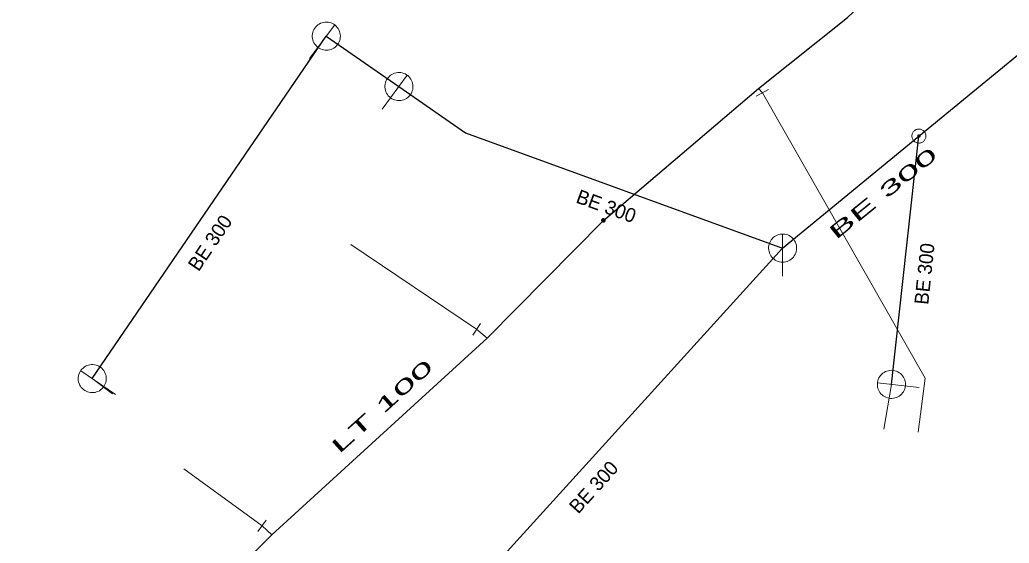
# Model space of a CAD drawing. Extents: x -791337 to -790755, y -988454 to -987923.
# Drawn here: x -791100.6 to -791030.1, y -988190.7 to -988153.5 of the extents above; entities that cross this region are included whole.
import ezdxf

# ---------------------------------------------------------------- set-up
doc = ezdxf.new("R2010")
doc.units = 0
doc.header["$LTSCALE"] = 0.4
for name, color, linetype, lineweight in [('1', 7, 'Continuous', 13), ('11', 7, 'Continuous', 13), ('13', 7, 'Continuous', 13), ('14', 7, 'Continuous', 25), ('17', 7, 'Continuous', 25), ('22', 7, 'Continuous', 13), ('31', 7, 'Continuous', 13), ('34', 7, 'Continuous', 13), ('9', 7, 'Continuous', 13)]:
    doc.layers.add(name, color=color, linetype=linetype, lineweight=lineweight)

msp = doc.modelspace()

# ---------------------------------------------------------------- linework, layer by layer
at = {"layer": '11'}
for p, q in [((-791093.973, -988180.094), (-791095.423, -988179.006)), ((-791038.989, -988182.596), (-791038.46, -988179.417))]:
    msp.add_line(p, q, dxfattribs=at)
at = {"layer": '13'}
for p, q in [((-791068.026, -988175.492), (-791076.987, -988169.447)), ((-791067.283, -988176.118), (-791068.026, -988175.492)), ((-791083.315, -988189.494), (-791088.895, -988185.436)), ((-791082.624, -988190.124), (-791083.315, -988189.494))]:
    msp.add_line(p, q, dxfattribs=at)
msp.add_lwpolyline([(-791047.659, -988158.659), (-791036.061, -988178.975), (-791036.548, -988182.811)], dxfattribs=at)
at = {"layer": '14', "lineweight": 13}
msp.add_line((-791047.931, -988158.352), (-791047.659, -988158.659), dxfattribs=at)
at = {"layer": '14'}
msp.add_line((-791046.212, -988169.71), (-791036.499, -988161.736), dxfattribs=at)
for points in [[(-791038.46, -988179.417), (-791036.499, -988161.736), (-791017.401, -988146.056)], [(-791095.423, -988179.006), (-791078.737, -988154.618), (-791073.562, -988158.21)], [(-791073.562, -988158.21), (-791068.822, -988161.5), (-791046.212, -988169.71)], [(-791078.328, -988268.275), (-791076.412, -988241.781), (-791075.638, -988228.634), (-791074.254, -988200.572), (-791046.212, -988169.71)]]:
    msp.add_lwpolyline(points, dxfattribs=at)
at = {"layer": '17'}
for points in [[(-791058.988, -988167.736), (-791047.931, -988158.352), (-791041.594, -988153.292), (-791025.772, -988138.449), (-791015.996, -988126.782)], [(-791100.587, -988208.045), (-791094.248, -988201.857), (-791082.624, -988190.124), (-791067.283, -988176.118), (-791058.988, -988167.736)]]:
    msp.add_lwpolyline(points, dxfattribs=at)
at = {"layer": '22'}
for p, q in [((-791079.931, -988156.222), (-791078.14, -988153.816)), ((-791074.756, -988159.814), (-791072.965, -988157.408)), ((-791046.212, -988171.711), (-791046.211, -988168.711)), ((-791093.771, -988180.135), (-791096.247, -988178.441)), ((-791036.471, -988179.637), (-791039.453, -988179.306))]:
    msp.add_line(p, q, dxfattribs=at)
for points in [[(-791077.935, -988155.215), (-791077.874, -988155.124), (-791077.824, -988155.026), (-791077.785, -988154.924), (-791077.757, -988154.819), (-791077.741, -988154.71), (-791077.737, -988154.601), (-791077.745, -988154.491), (-791077.765, -988154.384), (-791077.796, -988154.278), (-791077.839, -988154.178), (-791077.892, -988154.082), (-791077.957, -988153.993), (-791078.029, -988153.912), (-791078.111, -988153.839), (-791078.2, -988153.774), (-791078.295, -988153.721), (-791078.396, -988153.677), (-791078.501, -988153.646), (-791078.609, -988153.626), (-791078.717, -988153.618), (-791078.827, -988153.622), (-791078.935, -988153.638), (-791079.042, -988153.666), (-791079.144, -988153.704), (-791079.241, -988153.754), (-791079.332, -988153.815), (-791079.417, -988153.885), (-791079.492, -988153.963), (-791079.56, -988154.05), (-791079.617, -988154.144), (-791079.664, -988154.242), (-791079.699, -988154.346), (-791079.723, -988154.452), (-791079.736, -988154.561), (-791079.735, -988154.671), (-791079.724, -988154.78), (-791079.7, -988154.887), (-791079.665, -988154.991), (-791079.619, -988155.09), (-791079.561, -988155.183), (-791079.495, -988155.27), (-791079.419, -988155.349), (-791079.335, -988155.42), (-791079.244, -988155.48), (-791079.146, -988155.53), (-791079.045, -988155.569), (-791078.938, -988155.597), (-791078.829, -988155.613), (-791078.72, -988155.617), (-791078.611, -988155.61), (-791078.503, -988155.591), (-791078.399, -988155.559), (-791078.298, -988155.517), (-791078.203, -988155.463), (-791078.113, -988155.4), (-791078.031, -988155.326), (-791077.958, -988155.245)], [(-791072.76, -988158.807), (-791072.699, -988158.716), (-791072.649, -988158.618), (-791072.61, -988158.516), (-791072.582, -988158.411), (-791072.566, -988158.302), (-791072.562, -988158.193), (-791072.57, -988158.083), (-791072.59, -988157.976), (-791072.621, -988157.87), (-791072.664, -988157.77), (-791072.717, -988157.674), (-791072.782, -988157.585), (-791072.854, -988157.504), (-791072.936, -988157.431), (-791073.025, -988157.366), (-791073.12, -988157.313), (-791073.221, -988157.269), (-791073.326, -988157.238), (-791073.434, -988157.218), (-791073.542, -988157.21), (-791073.652, -988157.214), (-791073.76, -988157.23), (-791073.867, -988157.258), (-791073.969, -988157.296), (-791074.066, -988157.346), (-791074.157, -988157.407), (-791074.242, -988157.477), (-791074.317, -988157.555), (-791074.385, -988157.642), (-791074.442, -988157.736), (-791074.489, -988157.834), (-791074.524, -988157.938), (-791074.548, -988158.044), (-791074.561, -988158.153), (-791074.56, -988158.263), (-791074.549, -988158.372), (-791074.525, -988158.479), (-791074.49, -988158.583), (-791074.444, -988158.682), (-791074.386, -988158.775), (-791074.32, -988158.862), (-791074.244, -988158.941), (-791074.16, -988159.012), (-791074.069, -988159.072), (-791073.971, -988159.122), (-791073.87, -988159.161), (-791073.763, -988159.189), (-791073.654, -988159.205), (-791073.545, -988159.209), (-791073.436, -988159.202), (-791073.328, -988159.183), (-791073.224, -988159.151), (-791073.123, -988159.109), (-791073.028, -988159.055), (-791072.938, -988158.992), (-791072.856, -988158.918), (-791072.783, -988158.837)], [(-791045.212, -988169.711), (-791045.217, -988169.602), (-791045.235, -988169.494), (-791045.265, -988169.388), (-791045.305, -988169.287), (-791045.357, -988169.19), (-791045.419, -988169.1), (-791045.491, -988169.017), (-791045.571, -988168.943), (-791045.659, -988168.877), (-791045.753, -988168.822), (-791045.853, -988168.777), (-791045.958, -988168.744), (-791046.065, -988168.722), (-791046.174, -988168.712), (-791046.284, -988168.714), (-791046.392, -988168.728), (-791046.499, -988168.753), (-791046.602, -988168.79), (-791046.7, -988168.839), (-791046.792, -988168.897), (-791046.878, -988168.966), (-791046.955, -988169.043), (-791047.024, -988169.129), (-791047.083, -988169.221), (-791047.131, -988169.319), (-791047.168, -988169.422), (-791047.194, -988169.529), (-791047.208, -988169.637), (-791047.211, -988169.747), (-791047.201, -988169.856), (-791047.18, -988169.963), (-791047.146, -988170.067), (-791047.102, -988170.167), (-791047.047, -988170.262), (-791046.981, -988170.35), (-791046.907, -988170.43), (-791046.824, -988170.502), (-791046.734, -988170.564), (-791046.638, -988170.616), (-791046.536, -988170.657), (-791046.431, -988170.687), (-791046.323, -988170.705), (-791046.213, -988170.711), (-791046.104, -988170.705), (-791045.996, -988170.687), (-791045.891, -988170.658), (-791045.789, -988170.617), (-791045.692, -988170.565), (-791045.602, -988170.503), (-791045.519, -988170.432), (-791045.444, -988170.352), (-791045.379, -988170.264), (-791045.323, -988170.17), (-791045.279, -988170.07), (-791045.245, -988169.966), (-791045.223, -988169.858), (-791045.213, -988169.749)], [(-791094.857, -988178.18), (-791094.951, -988178.124), (-791095.05, -988178.078), (-791095.154, -988178.043), (-791095.26, -988178.019), (-791095.37, -988178.007), (-791095.479, -988178.007), (-791095.588, -988178.02), (-791095.695, -988178.044), (-791095.799, -988178.079), (-791095.897, -988178.126), (-791095.991, -988178.183), (-791096.077, -988178.251), (-791096.156, -988178.327), (-791096.226, -988178.411), (-791096.286, -988178.503), (-791096.336, -988178.6), (-791096.375, -988178.703), (-791096.403, -988178.808), (-791096.418, -988178.917), (-791096.422, -988179.026), (-791096.414, -988179.136), (-791096.394, -988179.243), (-791096.362, -988179.348), (-791096.319, -988179.449), (-791096.265, -988179.544), (-791096.201, -988179.632), (-791096.127, -988179.714), (-791096.046, -988179.787), (-791095.956, -988179.851), (-791095.861, -988179.904), (-791095.761, -988179.947), (-791095.656, -988179.978), (-791095.548, -988179.998), (-791095.439, -988180.006), (-791095.329, -988180.001), (-791095.221, -988179.985), (-791095.115, -988179.958), (-791095.013, -988179.918), (-791094.916, -988179.868), (-791094.824, -988179.807), (-791094.74, -988179.738), (-791094.664, -988179.659), (-791094.597, -988179.571), (-791094.541, -988179.478), (-791094.495, -988179.379), (-791094.459, -988179.276), (-791094.435, -988179.168), (-791094.424, -988179.059), (-791094.424, -988178.95), (-791094.436, -988178.841), (-791094.459, -988178.734), (-791094.495, -988178.631), (-791094.541, -988178.531), (-791094.599, -988178.438), (-791094.666, -988178.352), (-791094.742, -988178.273), (-791094.827, -988178.203)], [(-791038.349, -988178.423), (-791038.458, -988178.417), (-791038.567, -988178.423), (-791038.676, -988178.441), (-791038.781, -988178.469), (-791038.883, -988178.51), (-791038.979, -988178.562), (-791039.069, -988178.624), (-791039.152, -988178.696), (-791039.227, -988178.776), (-791039.292, -988178.863), (-791039.348, -988178.958), (-791039.392, -988179.059), (-791039.426, -988179.162), (-791039.448, -988179.27), (-791039.458, -988179.379), (-791039.456, -988179.488), (-791039.443, -988179.597), (-791039.417, -988179.704), (-791039.38, -988179.806), (-791039.332, -988179.904), (-791039.273, -988179.997), (-791039.205, -988180.082), (-791039.127, -988180.16), (-791039.042, -988180.229), (-791038.95, -988180.288), (-791038.852, -988180.336), (-791038.748, -988180.374), (-791038.642, -988180.399), (-791038.533, -988180.413), (-791038.424, -988180.416), (-791038.315, -988180.406), (-791038.208, -988180.384), (-791038.104, -988180.351), (-791038.003, -988180.307), (-791037.909, -988180.251), (-791037.821, -988180.187), (-791037.74, -988180.112), (-791037.669, -988180.029), (-791037.606, -988179.94), (-791037.554, -988179.843), (-791037.513, -988179.742), (-791037.483, -988179.636), (-791037.465, -988179.528), (-791037.459, -988179.419), (-791037.465, -988179.309), (-791037.482, -988179.202), (-791037.512, -988179.096), (-791037.553, -988178.994), (-791037.605, -988178.898), (-791037.666, -988178.807), (-791037.737, -988178.724), (-791037.818, -988178.65), (-791037.905, -988178.584), (-791037.999, -988178.529), (-791038.099, -988178.484), (-791038.204, -988178.45), (-791038.311, -988178.428)]]:
    msp.add_lwpolyline(points, close=True, dxfattribs=at)
at = {"layer": '31'}
for points in [[(-791036.443, -988161.239), (-791036.495, -988161.236), (-791036.548, -988161.238), (-791036.599, -988161.246), (-791036.65, -988161.259), (-791036.699, -988161.278), (-791036.746, -988161.302), (-791036.79, -988161.33), (-791036.83, -988161.363), (-791036.868, -988161.399), (-791036.901, -988161.439), (-791036.93, -988161.483), (-791036.954, -988161.53), (-791036.973, -988161.578), (-791036.987, -988161.629), (-791036.995, -988161.68), (-791036.998, -988161.732), (-791036.996, -988161.785), (-791036.988, -988161.837), (-791036.975, -988161.887), (-791036.956, -988161.936), (-791036.932, -988161.983), (-791036.904, -988162.028), (-791036.871, -988162.068), (-791036.835, -988162.106), (-791036.795, -988162.138), (-791036.751, -988162.167), (-791036.704, -988162.192), (-791036.656, -988162.21), (-791036.605, -988162.224), (-791036.554, -988162.232), (-791036.502, -988162.235), (-791036.449, -988162.233), (-791036.397, -988162.226), (-791036.347, -988162.212), (-791036.298, -988162.193), (-791036.251, -988162.17), (-791036.207, -988162.142), (-791036.166, -988162.109), (-791036.128, -988162.072), (-791036.096, -988162.032), (-791036.067, -988161.988), (-791036.042, -988161.942), (-791036.024, -988161.893), (-791036.01, -988161.842), (-791036.002, -988161.791), (-791035.999, -988161.739), (-791036.001, -988161.686), (-791036.008, -988161.635), (-791036.022, -988161.584), (-791036.041, -988161.535), (-791036.064, -988161.488), (-791036.092, -988161.445), (-791036.125, -988161.404), (-791036.162, -988161.366), (-791036.202, -988161.333), (-791036.246, -988161.304), (-791036.292, -988161.28), (-791036.341, -988161.261), (-791036.392, -988161.247)], [(-791036.489, -988161.654), (-791036.498, -988161.653), (-791036.507, -988161.654), (-791036.515, -988161.655), (-791036.523, -988161.657), (-791036.531, -988161.66), (-791036.539, -988161.665), (-791036.546, -988161.669), (-791036.553, -988161.674), (-791036.559, -988161.681), (-791036.565, -988161.687), (-791036.569, -988161.694), (-791036.573, -988161.702), (-791036.576, -988161.71), (-791036.579, -988161.718), (-791036.58, -988161.726), (-791036.581, -988161.735), (-791036.58, -988161.744), (-791036.579, -988161.752), (-791036.577, -988161.76), (-791036.574, -988161.768), (-791036.569, -988161.776), (-791036.565, -988161.783), (-791036.56, -988161.79), (-791036.554, -988161.797), (-791036.547, -988161.802), (-791036.54, -988161.806), (-791036.532, -988161.81), (-791036.524, -988161.813), (-791036.516, -988161.816), (-791036.508, -988161.817), (-791036.499, -988161.818), (-791036.49, -988161.817), (-791036.482, -988161.816), (-791036.474, -988161.814), (-791036.466, -988161.811), (-791036.458, -988161.807), (-791036.451, -988161.802), (-791036.444, -988161.797), (-791036.437, -988161.791), (-791036.432, -988161.784), (-791036.428, -988161.777), (-791036.424, -988161.769), (-791036.421, -988161.761), (-791036.418, -988161.753), (-791036.417, -988161.745), (-791036.416, -988161.736), (-791036.417, -988161.727), (-791036.418, -988161.719), (-791036.42, -988161.711), (-791036.423, -988161.703), (-791036.427, -988161.695), (-791036.432, -988161.688), (-791036.437, -988161.681), (-791036.444, -988161.675), (-791036.45, -988161.669), (-791036.457, -988161.665), (-791036.465, -988161.661), (-791036.473, -988161.658), (-791036.481, -988161.655)]]:
    msp.add_lwpolyline(points, close=True, dxfattribs=at)
at = {"layer": '34'}
for p, q in [((-791047.22, -988158.419), (-791048.098, -988158.897)), ((-791067.746, -988175.077), (-791068.306, -988175.906)), ((-791083.021, -988189.089), (-791083.609, -988189.898))]:
    msp.add_line(p, q, dxfattribs=at)
at = {"layer": '9'}
for points in [[(-791059.114, -988167.736), (-791059.114, -988167.749), (-791059.112, -988167.762), (-791059.109, -988167.775), (-791059.104, -988167.787), (-791059.098, -988167.799), (-791059.091, -988167.81), (-791059.083, -988167.82), (-791059.073, -988167.83), (-791059.063, -988167.838), (-791059.052, -988167.845), (-791059.04, -988167.851), (-791059.028, -988167.856), (-791059.015, -988167.859), (-791059.002, -988167.861), (-791058.989, -988167.863), (-791058.976, -988167.862), (-791058.963, -988167.86), (-791058.95, -988167.857), (-791058.938, -988167.852), (-791058.926, -988167.846), (-791058.915, -988167.839), (-791058.905, -988167.831), (-791058.895, -988167.821), (-791058.887, -988167.811), (-791058.88, -988167.8), (-791058.874, -988167.788), (-791058.869, -988167.776), (-791058.866, -988167.763), (-791058.864, -988167.75), (-791058.862, -988167.737), (-791058.863, -988167.724), (-791058.865, -988167.711), (-791058.868, -988167.698), (-791058.873, -988167.686), (-791058.879, -988167.674), (-791058.886, -988167.663), (-791058.894, -988167.653), (-791058.904, -988167.643), (-791058.914, -988167.635), (-791058.925, -988167.628), (-791058.937, -988167.622), (-791058.949, -988167.617), (-791058.962, -988167.614), (-791058.975, -988167.612), (-791058.988, -988167.611), (-791059.001, -988167.611), (-791059.014, -988167.613), (-791059.027, -988167.616), (-791059.039, -988167.621), (-791059.051, -988167.627), (-791059.062, -988167.634), (-791059.072, -988167.642), (-791059.082, -988167.652), (-791059.09, -988167.662), (-791059.097, -988167.673), (-791059.103, -988167.685), (-791059.108, -988167.697), (-791059.111, -988167.71), (-791059.113, -988167.723)], [(-791059.094, -988167.736), (-791059.095, -988167.747), (-791059.093, -988167.758), (-791059.09, -988167.769), (-791059.086, -988167.779), (-791059.081, -988167.789), (-791059.075, -988167.798), (-791059.068, -988167.807), (-791059.06, -988167.815), (-791059.051, -988167.822), (-791059.042, -988167.828), (-791059.032, -988167.833), (-791059.022, -988167.837), (-791059.011, -988167.84), (-791059, -988167.843), (-791058.989, -988167.843), (-791058.978, -988167.843), (-791058.967, -988167.841), (-791058.956, -988167.838), (-791058.946, -988167.834), (-791058.936, -988167.829), (-791058.927, -988167.823), (-791058.918, -988167.816), (-791058.91, -988167.808), (-791058.903, -988167.799), (-791058.897, -988167.79), (-791058.892, -988167.78), (-791058.888, -988167.77), (-791058.885, -988167.759), (-791058.883, -988167.748), (-791058.882, -988167.737), (-791058.882, -988167.726), (-791058.884, -988167.715), (-791058.887, -988167.704), (-791058.891, -988167.694), (-791058.896, -988167.684), (-791058.902, -988167.675), (-791058.909, -988167.666), (-791058.917, -988167.658), (-791058.926, -988167.651), (-791058.935, -988167.645), (-791058.945, -988167.64), (-791058.955, -988167.636), (-791058.966, -988167.633), (-791058.977, -988167.631), (-791058.988, -988167.631), (-791058.999, -988167.63), (-791059.01, -988167.632), (-791059.021, -988167.635), (-791059.031, -988167.639), (-791059.041, -988167.644), (-791059.05, -988167.65), (-791059.059, -988167.657), (-791059.067, -988167.665), (-791059.074, -988167.674), (-791059.08, -988167.683), (-791059.085, -988167.693), (-791059.089, -988167.703), (-791059.092, -988167.714), (-791059.094, -988167.725)], [(-791059.075, -988167.736), (-791059.075, -988167.745), (-791059.074, -988167.754), (-791059.071, -988167.763), (-791059.068, -988167.771), (-791059.064, -988167.779), (-791059.059, -988167.787), (-791059.053, -988167.794), (-791059.047, -988167.8), (-791059.04, -988167.806), (-791059.032, -988167.811), (-791059.024, -988167.815), (-791059.016, -988167.818), (-791059.007, -988167.821), (-791058.998, -988167.822), (-791058.989, -988167.824), (-791058.98, -988167.823), (-791058.971, -988167.822), (-791058.962, -988167.819), (-791058.954, -988167.816), (-791058.946, -988167.812), (-791058.938, -988167.807), (-791058.931, -988167.801), (-791058.925, -988167.795), (-791058.919, -988167.788), (-791058.914, -988167.78), (-791058.91, -988167.772), (-791058.907, -988167.764), (-791058.904, -988167.755), (-791058.903, -988167.746), (-791058.901, -988167.737), (-791058.902, -988167.728), (-791058.903, -988167.719), (-791058.906, -988167.71), (-791058.909, -988167.702), (-791058.913, -988167.694), (-791058.918, -988167.686), (-791058.924, -988167.679), (-791058.93, -988167.673), (-791058.937, -988167.667), (-791058.945, -988167.662), (-791058.953, -988167.658), (-791058.961, -988167.655), (-791058.97, -988167.652), (-791058.979, -988167.651), (-791058.988, -988167.65), (-791058.997, -988167.65), (-791059.006, -988167.651), (-791059.015, -988167.654), (-791059.023, -988167.657), (-791059.031, -988167.661), (-791059.039, -988167.666), (-791059.046, -988167.672), (-791059.052, -988167.678), (-791059.058, -988167.685), (-791059.063, -988167.693), (-791059.067, -988167.701), (-791059.07, -988167.709), (-791059.073, -988167.718), (-791059.074, -988167.727)], [(-791059.055, -988167.736), (-791059.055, -988167.743), (-791059.054, -988167.75), (-791059.053, -988167.757), (-791059.05, -988167.763), (-791059.047, -988167.769), (-791059.043, -988167.775), (-791059.039, -988167.781), (-791059.034, -988167.786), (-791059.028, -988167.79), (-791059.022, -988167.794), (-791059.016, -988167.797), (-791059.01, -988167.8), (-791059.003, -988167.801), (-791058.996, -988167.804), (-791058.989, -988167.804), (-791058.982, -988167.804), (-791058.975, -988167.802), (-791058.968, -988167.801), (-791058.962, -988167.798), (-791058.955, -988167.795), (-791058.95, -988167.791), (-791058.944, -988167.787), (-791058.939, -988167.782), (-791058.935, -988167.776), (-791058.931, -988167.77), (-791058.928, -988167.764), (-791058.925, -988167.758), (-791058.923, -988167.751), (-791058.922, -988167.744), (-791058.921, -988167.737), (-791058.921, -988167.73), (-791058.922, -988167.723), (-791058.924, -988167.716), (-791058.927, -988167.71), (-791058.93, -988167.703), (-791058.934, -988167.698), (-791058.938, -988167.692), (-791058.943, -988167.687), (-791058.949, -988167.683), (-791058.954, -988167.679), (-791058.961, -988167.676), (-791058.967, -988167.673), (-791058.974, -988167.671), (-791058.981, -988167.67), (-791058.988, -988167.67), (-791058.995, -988167.67), (-791059.002, -988167.67), (-791059.009, -988167.672), (-791059.015, -988167.675), (-791059.021, -988167.678), (-791059.027, -988167.682), (-791059.033, -988167.686), (-791059.038, -988167.691), (-791059.042, -988167.697), (-791059.046, -988167.702), (-791059.049, -988167.709), (-791059.052, -988167.715), (-791059.053, -988167.722), (-791059.055, -988167.729)], [(-791059.035, -988167.736), (-791059.035, -988167.741), (-791059.035, -988167.746), (-791059.034, -988167.751), (-791059.032, -988167.755), (-791059.03, -988167.76), (-791059.027, -988167.764), (-791059.024, -988167.767), (-791059.02, -988167.771), (-791059.017, -988167.774), (-791059.013, -988167.777), (-791059.008, -988167.779), (-791059.004, -988167.781), (-791058.999, -988167.782), (-791058.994, -988167.784), (-791058.989, -988167.784), (-791058.984, -988167.784), (-791058.979, -988167.783), (-791058.974, -988167.782), (-791058.97, -988167.78), (-791058.965, -988167.778), (-791058.961, -988167.775), (-791058.957, -988167.772), (-791058.954, -988167.768), (-791058.951, -988167.765), (-791058.948, -988167.761), (-791058.946, -988167.756), (-791058.944, -988167.752), (-791058.943, -988167.747), (-791058.942, -988167.742), (-791058.941, -988167.737), (-791058.941, -988167.732), (-791058.942, -988167.727), (-791058.943, -988167.722), (-791058.945, -988167.718), (-791058.947, -988167.713), (-791058.95, -988167.709), (-791058.953, -988167.705), (-791058.956, -988167.702), (-791058.96, -988167.699), (-791058.964, -988167.696), (-791058.969, -988167.694), (-791058.973, -988167.692), (-791058.978, -988167.691), (-791058.983, -988167.69), (-791058.988, -988167.69), (-791058.993, -988167.69), (-791058.998, -988167.691), (-791059.003, -988167.691), (-791059.007, -988167.693), (-791059.012, -988167.695), (-791059.016, -988167.698), (-791059.019, -988167.701), (-791059.023, -988167.704), (-791059.026, -988167.708), (-791059.029, -988167.712), (-791059.031, -988167.717), (-791059.033, -988167.721), (-791059.034, -988167.726), (-791059.035, -988167.731)], [(-791059.015, -988167.736), (-791059.015, -988167.739), (-791059.016, -988167.742), (-791059.015, -988167.744), (-791059.014, -988167.747), (-791059.013, -988167.75), (-791059.011, -988167.752), (-791059.009, -988167.754), (-791059.007, -988167.756), (-791059.005, -988167.758), (-791059.003, -988167.76), (-791059, -988167.762), (-791058.997, -988167.763), (-791058.995, -988167.763), (-791058.992, -988167.764), (-791058.989, -988167.764), (-791058.986, -988167.764), (-791058.983, -988167.764), (-791058.98, -988167.763), (-791058.978, -988167.762), (-791058.975, -988167.761), (-791058.973, -988167.759), (-791058.97, -988167.757), (-791058.968, -988167.755), (-791058.967, -988167.753), (-791058.965, -988167.751), (-791058.964, -988167.748), (-791058.962, -988167.745), (-791058.962, -988167.743), (-791058.961, -988167.74), (-791058.96, -988167.737), (-791058.961, -988167.734), (-791058.961, -988167.731), (-791058.962, -988167.728), (-791058.963, -988167.726), (-791058.964, -988167.723), (-791058.966, -988167.721), (-791058.967, -988167.718), (-791058.969, -988167.716), (-791058.972, -988167.715), (-791058.974, -988167.713), (-791058.977, -988167.712), (-791058.979, -988167.711), (-791058.982, -988167.71), (-791058.985, -988167.71), (-791058.988, -988167.709), (-791058.991, -988167.71), (-791058.994, -988167.709), (-791058.996, -988167.711), (-791058.999, -988167.711), (-791059.002, -988167.712), (-791059.004, -988167.714), (-791059.006, -988167.715), (-791059.008, -988167.717), (-791059.01, -988167.72), (-791059.012, -988167.722), (-791059.013, -988167.725), (-791059.014, -988167.727), (-791059.015, -988167.73), (-791059.015, -988167.733)], [(-791058.996, -988167.736), (-791058.996, -988167.738), (-791058.996, -988167.738), (-791058.995, -988167.738), (-791058.995, -988167.74), (-791058.996, -988167.741), (-791058.994, -988167.741), (-791058.994, -988167.741), (-791058.994, -988167.743), (-791058.994, -988167.743), (-791058.993, -988167.744), (-791058.991, -988167.744), (-791058.991, -988167.744), (-791058.991, -988167.745), (-791058.989, -988167.745), (-791058.989, -988167.745), (-791058.988, -988167.745), (-791058.987, -988167.745), (-791058.987, -988167.744), (-791058.986, -988167.744), (-791058.984, -988167.744), (-791058.984, -988167.743), (-791058.984, -988167.743), (-791058.983, -988167.742), (-791058.983, -988167.742), (-791058.981, -988167.741), (-791058.981, -988167.74), (-791058.98, -988167.739), (-791058.98, -988167.739), (-791058.98, -988167.738), (-791058.98, -988167.737), (-791058.98, -988167.736), (-791058.98, -988167.735), (-791058.98, -988167.735), (-791058.981, -988167.734), (-791058.981, -988167.733), (-791058.982, -988167.732), (-791058.982, -988167.732), (-791058.983, -988167.731), (-791058.983, -988167.731), (-791058.984, -988167.73), (-791058.985, -988167.73), (-791058.986, -988167.729), (-791058.986, -988167.729), (-791058.987, -988167.729), (-791058.988, -988167.729), (-791058.989, -988167.729), (-791058.99, -988167.729), (-791058.99, -988167.729), (-791058.991, -988167.73), (-791058.992, -988167.729), (-791058.993, -988167.731), (-791058.993, -988167.731), (-791058.994, -988167.731), (-791058.994, -988167.731), (-791058.995, -988167.733), (-791058.995, -988167.734), (-791058.995, -988167.735), (-791058.996, -988167.735), (-791058.996, -988167.736)]]:
    msp.add_lwpolyline(points, close=True, dxfattribs=at)

# ---------------------------------------------------------------- texts
at = {"layer": '1'}
for s, rotation, width, p in [('BE 300', 39, 2.15, (-791042.414, -988169.161)), ('LT 100', 42, 2.2, (-791077.832, -988184.415))]:
    msp.add_text(s, height=1, rotation=rotation, dxfattribs=dict(at, width=width)).set_placement(p)
for rotation, p in [(340, (-791061.014, -988166.448)), (56, (-791087.838, -988171.435)), (84, (-791035.836, -988173.777)), (48, (-791060.78, -988188.696))]:
    msp.add_text('BE 300', height=1, rotation=rotation, dxfattribs=at).set_placement(p)

doc.saveas('drawing.dxf')
